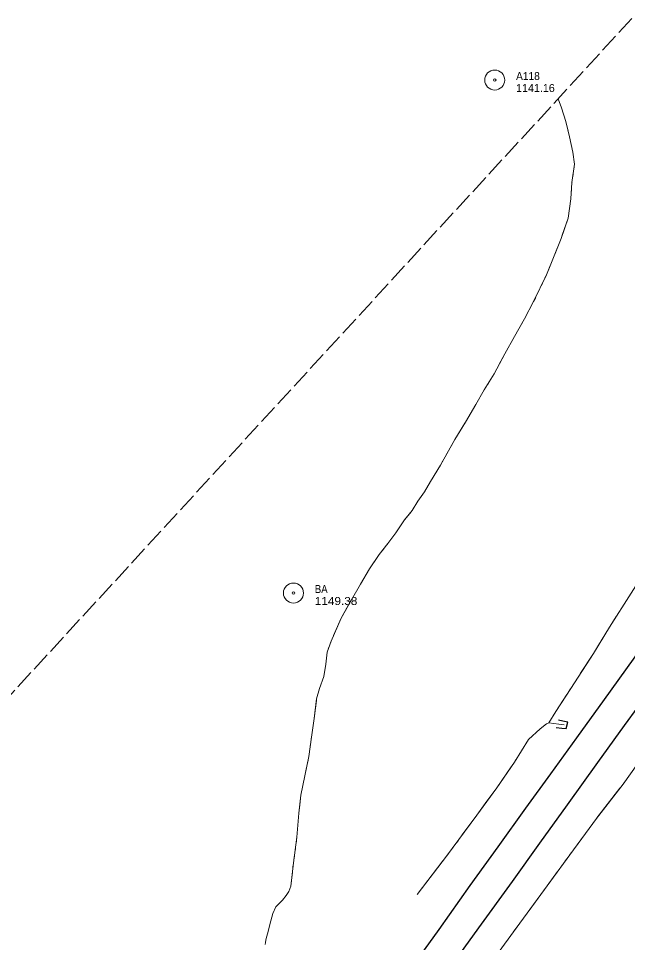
# Model space of a CAD drawing. Extents: x 300582 to 302999, y 51302 to 53600.
# Drawn here: x 301496 to 301953, y 52259 to 52952 of the extents above; entities that cross this region are included whole.
import ezdxf

# ---------------------------------------------------------------- set-up
doc = ezdxf.new("R2010")
doc.units = 0
doc.header["$LTSCALE"] = 2.4
doc.linetypes.add('LONG_DASHED', pattern=[7.5, 6, -1.5])
for name, color, linetype, lineweight in [('11', 7, 'Continuous', 25), ('15', 7, 'Continuous', 13), ('19', 7, 'Continuous', 13), ('4', 7, 'Continuous', 13), ('6', 7, 'Continuous', 13)]:
    doc.layers.add(name, color=color, linetype=linetype, lineweight=lineweight)

msp = doc.modelspace()

# ---------------------------------------------------------------- linework, layer by layer
at = {"layer": '11'}
for points in [[(301790.631, 52240.188), (301811.362, 52268.952), (301834.758, 52301.902), (301855.568, 52330.847), (301876.524, 52359.962), (301895.034, 52385.599), (301914.633, 52412.642), (301935.324, 52441.425), (301962.819, 52479.632), (301985.088, 52510.301), (302013.182, 52549.479), (302035.259, 52580.267), (302059.745, 52614.271), (302085.845, 52650.072), (302106.047, 52677.908), (302129.22, 52710.139), (302151.517, 52741.398), (302166.099, 52761.911), (302177.391, 52776.932)], [(301819.169, 52239.529), (301841.265, 52270.036), (301866.294, 52304.928), (301887.003, 52333.725), (301907.637, 52362.366), (301930.485, 52394.198), (301950.448, 52421.855), (301970.827, 52449.98), (301991.782, 52478.95), (302013.431, 52509.265), (302038.019, 52543.286), (302054.779, 52566.538), (302080.08, 52602.004), (302101.586, 52631.767), (302122.935, 52661.135), (302147.043, 52694.203), (302168.841, 52724.743), (302184.37, 52746.358), (302194.801, 52761.275)]]:
    msp.add_lwpolyline(points, dxfattribs=at)
at = {"layer": '15', "lineweight": 25}
msp.add_lwpolyline([(301899.026, 52420.333), (301903.374, 52419.817), (301906.596, 52419.543), (301907.812, 52424.441), (301904.174, 52425.255), (301900.87, 52425.846)], dxfattribs=at)
at = {"layer": '19'}
for p, q in [((301911.565, 52833.303), (301911.837, 52835.27)), ((301910.456, 52821.443), (301910.591, 52823.424)), ((301890.66, 52757.318), (301891.519, 52759.109)), ((301888.083, 52751.944), (301888.942, 52753.735)), ((301885.506, 52746.571), (301886.365, 52748.362)), ((301853.446, 52687.129), (301854.382, 52688.882)), ((301850.412, 52682.002), (301851.45, 52683.695)), ((301847.296, 52676.92), (301848.334, 52678.614)), ((301813.289, 52618.563), (301814.257, 52620.298)), ((301810.217, 52613.457), (301811.262, 52615.146)), ((301807.082, 52608.389), (301808.127, 52610.078)), ((301768.736, 52552.894), (301769.972, 52554.448)), ((301761.764, 52543.234), (301762.893, 52544.869)), ((301765.151, 52548.138), (301766.28, 52549.772)), ((301951.578, 52515.262), (301952.509, 52516.721)), ((301948.786, 52510.884), (301949.716, 52512.343)), ((301945.993, 52506.506), (301946.924, 52507.965)), ((301726.931, 52472.322), (301727.16, 52474.295)), ((301727.938, 52478.169), (301728.6, 52480.042)), ((301911.827, 52452.348), (301912.771, 52453.799)), ((301914.659, 52456.701), (301915.603, 52458.152)), ((301908.995, 52447.996), (301909.939, 52449.446)), ((301714.756, 52406.081), (301715.004, 52408.052)), ((301874.817, 52405.633), (301875.976, 52407.481)), ((301714.012, 52400.167), (301714.26, 52402.138)), ((301871.337, 52400.088), (301872.497, 52401.936)), ((301712.886, 52394.32), (301713.305, 52396.261)), ((301867.857, 52394.542), (301869.017, 52396.391)), ((301929.541, 52352.543), (301946.956, 52374.767)), ((301824.595, 52334.259), (301825.895, 52336.012)), ((301703.418, 52327.556), (301703.679, 52329.526)), ((301820.696, 52328.998), (301821.996, 52330.752)), ((301702.635, 52321.647), (301702.896, 52323.616)), ((301905.965, 52320.328), (301907.114, 52321.901)), ((301909.411, 52325.046), (301910.559, 52326.618)), ((301701.884, 52315.733), (301702.124, 52317.706)), ((301794.882, 52295.158), (301814.138, 52320.275)), ((301902.519, 52315.611), (301903.668, 52317.183)), ((301863.467, 52262.149), (301864.605, 52263.729))]:
    msp.add_line(p, q, dxfattribs=at)
for points in [[(301681.115, 52257.717), (301681.731, 52262.084), (301683.192, 52267.273), (301684.559, 52272.716), (301686.883, 52281.007), (301689.05, 52285.907), (301693.9, 52290.809), (301696.833, 52294.301), (301698.811, 52297.471), (301700.148, 52301.506), (301702.263, 52318.843), (301704.811, 52338.071), (301706.312, 52356.039), (301707.698, 52369.659), (301710.684, 52384.123), (301713.823, 52398.661), (301715.653, 52413.209), (301717.754, 52427.059), (301719.55, 52441.767), (301721.747, 52449.669), (301724.92, 52458.722), (301726.403, 52467.784), (301727.45, 52476.789), (301730.393, 52485.115), (301737.957, 52502.281), (301745.728, 52516.184), (301752.449, 52527.843), (301759.142, 52539.439), (301766.469, 52550.045), (301773.027, 52558.287), (301778.939, 52566.49), (301785.579, 52576.024), (301791.317, 52583.247), (301795.509, 52590.166), (301800.422, 52597.018), (301804.925, 52604.903), (301812.481, 52617.116), (301823.187, 52636.295), (301831.073, 52649.37), (301838.901, 52662.713), (301845.258, 52673.597), (301852.71, 52685.75), (301860.671, 52700.664), (301867.992, 52713.69), (301875.357, 52726.868), (301882.247, 52739.775), (301891.904, 52759.912), (301902.841, 52787.044), (301908.029, 52802.31), (301910.138, 52816.798), (301910.976, 52829.052), (301912.883, 52842.817), (301911.679, 52851.947), (301909.107, 52863.263), (301906.488, 52874.965), (301903.15, 52885.129), (301900.543, 52891.853)], [(301908.158, 52867.504), (301906.488, 52874.965), (301903.15, 52885.129), (301900.543, 52891.853)], [(301912.383, 52839.205), (301912.883, 52842.817), (301911.679, 52851.947), (301909.107, 52863.263), (301908.158, 52867.504)], [(301910.862, 52827.388), (301910.976, 52829.052), (301911.02, 52829.367)], [(301903.69, 52789.543), (301908.029, 52802.31), (301910.138, 52816.798), (301910.185, 52817.479)], [(301893.057, 52762.771), (301902.841, 52787.044), (301903.69, 52789.543)], [(301870.18, 52717.605), (301875.357, 52726.868), (301882.247, 52739.775), (301883.788, 52742.988)], [(301856.253, 52692.388), (301860.671, 52700.664), (301867.992, 52713.69), (301870.18, 52717.605)], [(301830.655, 52648.676), (301831.073, 52649.37), (301838.901, 52662.713), (301845.22, 52673.532)], [(301816.194, 52623.767), (301823.187, 52636.295), (301830.655, 52648.676)], [(301789.401, 52580.835), (301791.317, 52583.247), (301795.509, 52590.166), (301800.422, 52597.018), (301804.925, 52604.903), (301804.991, 52605.01)], [(301893.643, 52423.917), (301898.802, 52432.342), (301910.08, 52449.662), (301927.094, 52475.816), (301939.111, 52495.715), (301955.302, 52521.101), (301969.796, 52543.795), (301980.589, 52565.153), (301990.538, 52580.567), (301993.861, 52584.665), (301998.139, 52591.278), (301999.656, 52593.244), (302006.211, 52589.33)], [(301772.446, 52557.556), (301773.027, 52558.287), (301778.939, 52566.49), (301785.579, 52576.024), (301789.401, 52580.835)], [(301745.083, 52515.031), (301745.728, 52516.184), (301752.449, 52527.843), (301759.142, 52539.439), (301759.506, 52539.966)], [(301732.229, 52489.283), (301737.957, 52502.281), (301745.083, 52515.031)], [(301930.964, 52482.225), (301939.111, 52495.715), (301944.132, 52503.587)], [(301729.924, 52483.789), (301730.393, 52485.115), (301730.627, 52485.646)], [(301917.491, 52461.054), (301927.094, 52475.816), (301930.964, 52482.225)], [(301719.4, 52440.538), (301719.55, 52441.767), (301721.747, 52449.669), (301724.92, 52458.722), (301726.403, 52467.784), (301726.472, 52468.374)], [(301715.5, 52411.995), (301715.653, 52413.209), (301717.754, 52427.059), (301719.4, 52440.538)], [(301893.643, 52423.917), (301898.802, 52432.342), (301907.106, 52445.094)], [(301794.882, 52295.158), (301816.912, 52323.893), (301839.792, 52354.762), (301854.586, 52375.141), (301867.807, 52394.462), (301878.397, 52411.339), (301887.059, 52419.369), (301891.836, 52423.059), (301893.643, 52423.917), (301901.163, 52422.982), (301905.137, 52422.456)], [(301878.296, 52411.178), (301878.397, 52411.339), (301887.059, 52419.369), (301891.836, 52423.059), (301893.643, 52423.917), (301901.163, 52422.982), (301905.137, 52422.456)], [(301791.906, 52163.721), (301809.482, 52187.79), (301830.94, 52216.555), (301851.723, 52245.836), (301871.798, 52273.721), (301892.388, 52301.74), (301912.128, 52328.766), (301929.268, 52352.195), (301949.377, 52377.856), (301960.301, 52393.412), (301966.147, 52402.343), (301967.688, 52405.372), (301968.679, 52409.012), (301959.948, 52410.257)], [(301847.239, 52365.02), (301854.586, 52375.141), (301865.395, 52390.938)], [(301706.933, 52362.14), (301707.698, 52369.659), (301710.684, 52384.123), (301712.047, 52390.437)], [(301949.358, 52377.832), (301949.377, 52377.856), (301950.478, 52379.424)], [(301828.494, 52339.519), (301839.792, 52354.762), (301847.239, 52365.02)], [(301704.201, 52333.465), (301704.811, 52338.071), (301706.312, 52356.039), (301706.933, 52362.14)], [(301912.857, 52329.763), (301929.268, 52352.195), (301929.541, 52352.543)], [(301816.794, 52323.739), (301816.912, 52323.893), (301818.096, 52325.491)], [(301689.753, 52286.618), (301693.9, 52290.809), (301696.833, 52294.301), (301698.811, 52297.471), (301700.148, 52301.506), (301701.402, 52311.789)], [(301883.533, 52289.69), (301892.388, 52301.74), (301900.222, 52312.466)], [(301866.88, 52266.89), (301871.798, 52273.721), (301883.533, 52289.69)], [(301681.334, 52259.273), (301681.731, 52262.084), (301683.192, 52267.273), (301684.559, 52272.716), (301686.883, 52281.007), (301689.05, 52285.907), (301689.753, 52286.618)]]:
    msp.add_lwpolyline(points, dxfattribs=at)
at = {"layer": '4', "linetype": 'LONG_DASHED'}
msp.add_line((301955.887, 52952.13), (301210.553, 52140.364), dxfattribs=at)
at = {"layer": '6'}
for centre, radius in [((301853.085, 52905.971), 7.5), ((301853.085, 52905.971), 0.96), ((301702.224, 52521.256), 7.5), ((301702.224, 52521.256), 0.96)]:
    msp.add_circle(centre, radius, dxfattribs=at)

# ---------------------------------------------------------------- texts
for s, width, p in [('A118', 0.95, (301869.085, 52905.971)), ('BA', 0.9, (301718.224, 52521.256)), ('1149.38', 1.1, (301718.224, 52512.256))]:
    msp.add_text(s, height=6, dxfattribs=dict(at, width=width)).set_placement(p)
msp.add_text('1141.16', height=6, dxfattribs=at).set_placement((301869.085, 52896.971))

doc.saveas('drawing.dxf')
